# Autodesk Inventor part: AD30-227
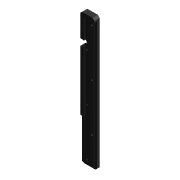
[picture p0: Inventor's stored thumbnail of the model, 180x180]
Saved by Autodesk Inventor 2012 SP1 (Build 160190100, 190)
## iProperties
Shininess: 0.0
Created: 2000-06
Part Number: AD30-227
Description: GUIDE RAIL
Document SubType Name: Modeling
Designer: Ron
Material: Delrin, Black
Density: 1.425 g/cm^3
Density: 0.0
Volumn: 0.0
Area: 0.0
PropertySet Name: Model Information
Control State: 0
Master: False
Checked Out: False
Title: GUIDE RAIL
Author: Ron
Revision Number: 01
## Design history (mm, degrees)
node "Extrusion1" dims "d2" = 19.05, "d3" = 0
  sketch "Sketch1"
    geometry: L1 (-50.8, 0)-(0, 0); L2 (0, 0)-(0, -475); L3 (0, -475)-(-50.8, -475); L4 (-50.8, -475)-(-50.8, 0); 1 further point
    constraints: 8 end point, 2 parallel, 1 coincident, 1 horizontal, 1 perpendicular
    dimensions: "d0" = 50.8 distance of L2.end L3.end; "d1" = 475 distance of L3.end L1.start
node "Extrusion2" dims "d6" = 6.35, "d7" = 0
  sketch "Sketch2"
    geometry: L1 (-50.8, 0)-(0, 0) reference; L2 (-50.8, -475)-(-50.8, 0) reference; L3 (0, -475)-(-50.8, -475) reference; L4 (0, 0)-(0, -475) reference; L5 (0, -12.7)-(-38.1, -12.7); L6 (-38.1, -12.7)-(-38.1, -475); L7 (-38.1, -475)-(0, -475); L8 (0, -475)-(0, -12.7)
    constraints: 8 end point, 2 parallel, 2 point on line, 1 horizontal, 1 perpendicular
    dimensions: "d4" = 12.7 distance between parallel lines of L2 L6; "d5" = 12.7 distance between parallel lines of L1 L5
node "Fillet1" dims "d8" = 6.35
node "Hole1" dims "d11" = 4.2, "d12" = 8, "d13" = 4.5, "d14" = 60 deg, "d15" = 8, "d16" = 118 deg
  sketch "Sketch3"
    geometry: L1 (0, -475)-(-38.1, -475) reference; L2 (0, -12.7)-(0, -475) reference; 1 further point
    dimensions: "d9" = 20 distance from line of point (-33, -455) L1; "d10" = 33 distance from line of L2 point (-33, -455)
node "Rectangular Pattern1" dims "d17" = 20, "d19" = 18, "d20" = 60, "d22" = 85
node "Chamfer1" dims "d23" = 6.35, "d24" = 6.35, "d59" = 45 deg
node "Chamfer2" dims "d25" = 6.35, "d26" = 30 deg, "d60" = 6.35
node "Extrusion3" dims "d29" = 6.35, "d30" = 0
  sketch "Sketch4"
    geometry: L1 (44.45, 12.7)-(6.35, 12.7) reference; L2 (44.45, 0)-(44.45, 12.7) reference; L3 (44.45, 12.7)-(35.45, 12.7); L4 (35.45, 12.7)-(35.45, 10.2); L5 (35.45, 10.2)-(44.45, 10.2); L6 (44.45, 10.2)-(44.45, 12.7)
    constraints: 8 end point, 2 parallel, 1 horizontal, 1 perpendicular
    dimensions: "d27" = 2.5 distance between parallel lines of L1 L5; "d28" = 9 distance between parallel lines of L4 L2
node "Fillet2" dims "d31" = 6.35
node "Extrusion4" dims "d34" = 6, "d35" = 0
  sketch "Sketch5"
    geometry: L1 (-38.1, -475)-(-44.45, -475) reference; L2 (-38.1, -475)-(-38.1, -19.05) reference; L3 (-50.8, -468.65)-(-50.8, -6.35) reference; L4 (-38.1, -322)-(-50.8, -322); L5 (-50.8, -322)-(-50.8, -475); L6 (-50.8, -475)-(-38.1, -475); L7 (-38.1, -475)-(-38.1, -322)
    constraints: 8 end point, 2 parallel, 2 point on line, 1 collinear, 1 horizontal, 1 perpendicular
    dimensions: "d55" = 153 distance between parallel lines of L1 L4
node "Chamfer3" dims "d36" = 2, "d37" = 2, "d61" = 45 deg
node "Extrusion5" dims "d41" = 8, "d42" = 0
  sketch "Sketch6"
    geometry: L1 (-31.75, -12.7)-(0, -12.7) reference; L2 (-50.8, -320)-(-50.8, -6.35) reference; L3 (-43.125, -84.675)-(-50.8, -84.675); L4 (-33.6, -94.2)-(-33.6, -99.2); L5 (-43.125, -108.725)-(-50.8, -108.725); L6 (-50.8, -84.675)-(-50.8, -108.725); A1 r 9.525 centre (-43.125, -99.2) between (-43.125, -108.725) and (-33.6, -99.2); A2 r 9.525 centre (-43.125, -94.2) between (-33.6, -94.2) and (-43.125, -84.675)
    constraints: 8 end point, 4 point on circle, 4 tangent, 2 centre point, 2 collinear, 2 point on line, 1 equal radius, 1 horizontal, 1 parallel, 1 perpendicular, 1 vertical alignment
    dimensions: "d39" = 81.5 distance from line of L1 A2.centre; "d50" = 5 distance of A2.centre A1.centre; "d53" = 9.525 radius of A2; "d54" = 17.2 distance between parallel lines of L2 L4
node "Hole2" dims "d44" = 2.459, "d45" = 4, "d46" = 2, "d47" = 60 deg, "d48" = 8, "d49" = 118 deg, "d58" = 6
  sketch "Sketch7"
    geometry: L1 (0, 0)-(0, -78.325) reference; L2 (19.05, 6.35)-(0, 6.35) reference; 2 further points
    constraints: 1 vertical alignment
    dimensions: "d43" = 38.1 distance of point (14, -58.95) point (14, -20.85); "d51" = 27.2 distance from line of L2 point (14, -20.85); "d52" = 14 distance from line of L1 point (14, -20.85)
node "Extrusion6" dims "d56" = 10, "d57" = 0
  sketch "Sketch8"
    geometry: L1 (0, 6.35)-(0, 0) reference; L2 (3.666, 0)-(0, 0) reference; L3 (0, 6.35)-(3.666, 0) reference
body "Solid1"
other parameters: "d38" = 19.304
